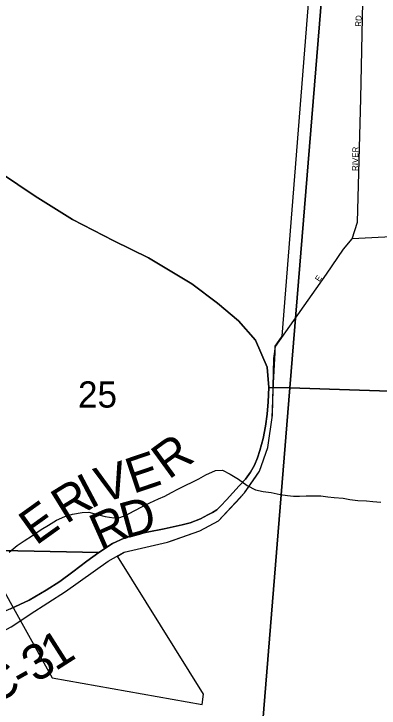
# Model space of a CAD drawing. Extents: x 1310247 to 1552180, y 377264 to 706493.
# Drawn here: x 1372833 to 1375909, y 486127 to 491975 of the extents above; entities that cross this region are included whole.
import ezdxf

# ---------------------------------------------------------------- set-up
doc = ezdxf.new("R2010")
doc.units = 0
for name, color, linetype in [('GM_X_City_Street', 7, 'Continuous'), ('GM_X_City_Street_Text', 7, 'Continuous'), ('GM_X_Corporation', 7, 'Continuous'), ('GM_X_County_Road', 7, 'Continuous'), ('GM_X_County_Road_Text', 7, 'Continuous'), ('GM_X_Minor_River', 7, 'Continuous'), ('GM_X_Section', 7, 'Continuous'), ('GM_X_Section_Text', 7, 'Continuous')]:
    doc.layers.add(name, color=color, linetype=linetype)

msp = doc.modelspace()

# ---------------------------------------------------------------- linework, layer by layer
at = {"layer": 'GM_X_City_Street'}
for points in [[(1374750.8, 487912.4), (1374776.6, 487940.1), (1374902.9, 488122.1), (1374971.4, 488323.4), (1375011.3, 488593.5), (1375021.6, 489073.1), (1375037.8, 489173.1), (1375466.1, 489782.4), (1375609.1, 489994.1), (1375683.2, 490078.9), (1375728.4, 490220.4), (1375754.8, 491261.6), (1375772.4, 492076.2), (1375835.7, 492588.6), (1375838.8, 492613.5)], [(1376450.1, 490120.6), (1375683.2, 490078.9)]]:
    msp.add_lwpolyline(points, dxfattribs=at)
at = {"layer": 'GM_X_Corporation'}
msp.add_lwpolyline([(1372670.3, 487253), (1373156, 486381.8), (1374419.7, 486157.1), (1374430, 486244.6), (1373704.6, 487408.3), (1373762.9, 487441.4), (1374127.8, 487524.1), (1374400.7, 487620.8), (1374556.9, 487703.8), (1374701, 487858.8), (1374776.6, 487940.1), (1374868.7, 488073.7), (1374902.9, 488122.1), (1374971.4, 488323.4), (1375007.6, 488573.7), (1375020.8, 488865.3), (1375034, 489123.8), (1375033.4, 489175.1), (1375092.3, 489259.4), (1375496.8, 494371.1)], dxfattribs=at)
at = {"layer": 'GM_X_County_Road'}
for points in [[(1374200, 487549.7), (1374400.7, 487620.8), (1374556.9, 487703.8), (1374741.2, 487902), (1374750.8, 487912.4)], [(1372970.9, 486917.2), (1373268.3, 487110.5), (1373626.8, 487364), (1373762.9, 487441.4), (1374127.8, 487524.1), (1374186.2, 487544.8), (1374200, 487549.7)], [(1372470.8, 486645.1), (1372561, 486679.8), (1372810.6, 486813), (1372950.1, 486903.7), (1372970.9, 486917.2)]]:
    msp.add_lwpolyline(points, dxfattribs=at)
at = {"layer": 'GM_X_Minor_River'}
msp.add_lwpolyline([(1372792.2, 487440.7), (1372860, 487497.1), (1372919.2, 487535.7), (1372988.7, 487580.1), (1373064.3, 487630.3), (1373123.5, 487666.8), (1373190.9, 487711.2), (1373262, 487741.5), (1373326.7, 487759.8), (1373407.3, 487773.7), (1373465.6, 487776.2), (1373537.4, 487758.2), (1373603.2, 487742.3), (1373675.1, 487730.3), (1373725.3, 487733), (1373780.1, 487753.6), (1373845.3, 487790), (1373916.5, 487826.3), (1373977.5, 487856.8), (1374050.7, 487891), (1374103.5, 487913.7), (1374160.5, 487942.3), (1374213.5, 487971), (1374276.5, 488003.5), (1374339.6, 488033.9), (1374390.4, 488058.7), (1374449.5, 488091.2), (1374530.8, 488129.2), (1374591.1, 488131.6), (1374654.4, 488097.7), (1374725.5, 488055.6), (1374798.3, 488001.4), (1374867.5, 487965.4), (1374931.4, 487951.6), (1374999.4, 487943.7), (1375077.2, 487927.6), (1375137.2, 487917.9), (1375187.2, 487912.5), (1375239.4, 487913.1), (1375293.6, 487915.7), (1375365.9, 487915.8), (1375418, 487914.3), (1375476, 487906.8), (1375530, 487901.3), (1375606.1, 487895.2), (1375664, 487883.6), (1375730, 487875.8), (1375804.2, 487871.8), (1375856.3, 487868.3), (1375924.3, 487860.5)], dxfattribs=at)
at = {"layer": 'GM_X_Section'}
for points in [[(1375560.3, 493789.5), (1381056.6, 494047.8), (1380602.9, 488643.8), (1375156.7, 488824.4)], [(1375156.7, 488824.4), (1380602.9, 488643.8), (1380084.6, 483209.4), (1374727.4, 483521.8)], [(1372181.4, 487466.3), (1373548.9, 487439), (1373447.2, 487365.3), (1373329.1, 487276), (1373219.2, 487192.5), (1373105.5, 487119.1), (1372961.6, 487036.4), (1372804, 486964), (1372644.4, 486895.7), (1372410.4, 486809), (1372380, 486791.7), (1372343.5, 486768.5), (1372305.2, 486757.4), (1372258.9, 486744.4), (1372166.5, 486726.6)]]:
    msp.add_lwpolyline(points, close=True, dxfattribs=at)
for points in [[(1375560.3, 493789.5), (1375156.7, 488824.4), (1374980.7, 488828.4), (1374966.6, 488998.7), (1374867.9, 489227), (1374725.6, 489390.3), (1374549, 489538.3), (1374332.7, 489701.3), (1373967.7, 489919.6), (1373674.9, 490064.3), (1373327, 490242.3), (1373013.5, 490439.5), (1372719.9, 490636.2)], [(1372719.9, 490636.2), (1373013.5, 490439.5), (1373327, 490242.3), (1373674.9, 490064.3), (1373967.7, 489919.6), (1374332.7, 489701.3), (1374549, 489538.3), (1374725.6, 489390.3), (1374867.9, 489227), (1374966.6, 488998.7), (1374980.7, 488828.4), (1374976, 488706.5), (1374967.6, 488602.7), (1374953.3, 488501), (1374932.9, 488399.4), (1374904.6, 488296.1), (1374885.2, 488234.5), (1374859.7, 488173.1), (1374826.4, 488113.8), (1374783.1, 488056.9), (1374729.7, 487998.1), (1374678.5, 487941.2), (1374625.1, 487882.4), (1374575.9, 487829.6), (1374541.2, 487798.3), (1374506.6, 487775.1), (1374466.2, 487754.1), (1374405.4, 487721.5), (1374318.6, 487687.4), (1374250.2, 487671), (1374099.5, 487638.4), (1373956.8, 487609.7), (1373854.3, 487588), (1373761.6, 487558.2), (1373664.6, 487512.4), (1373548.9, 487439), (1372181.4, 487466.3)], [(1372804, 486964), (1372961.6, 487036.4), (1373105.5, 487119.1), (1373219.2, 487192.5), (1373329.1, 487276), (1373447.2, 487365.3), (1373548.9, 487439), (1373664.6, 487512.4), (1373761.6, 487558.2), (1373854.3, 487588), (1373956.8, 487609.7), (1374099.5, 487638.4), (1374250.2, 487671), (1374318.6, 487687.4), (1374405.4, 487721.5), (1374466.2, 487754.1), (1374506.6, 487775.1), (1374541.2, 487798.3), (1374575.9, 487829.6), (1374625.1, 487882.4), (1374678.5, 487941.2), (1374729.7, 487998.1), (1374783.1, 488056.9), (1374826.4, 488113.8), (1374859.7, 488173.1), (1374885.2, 488234.5), (1374904.6, 488296.1), (1374932.9, 488399.4), (1374953.3, 488501), (1374967.6, 488602.7), (1374976, 488706.5), (1374980.7, 488828.4), (1375156.7, 488824.4), (1374727.4, 483521.8)]]:
    msp.add_lwpolyline(points, dxfattribs=at)

# ---------------------------------------------------------------- texts
at = {"layer": 'GM_X_City_Street_Text'}
for s, rotation, p in [('RD', 86.98614, (1375757.4, 491866.2)), ('RIVER', 88.89889, (1375731, 490651.5)), ('E', 56.31413, (1375407, 489714.9))]:
    msp.add_text(s, height=50, rotation=rotation, dxfattribs=at).set_placement(p)
at = {"layer": 'GM_X_County_Road_Text'}
for s, rotation, p in [('R', 36.07267, (1374137.1, 488046.8)), ('E', 18.73985, (1373838.4, 487930.1)), ('V', 16.18808, (1373571.2, 487852.2)), ('I', 27.95195, (1373477.5, 487800.5)), ('R', 31.69354, (1373272.3, 487673.7)), ('E', 35.66833, (1373019.5, 487492)), ('D', 15.45152, (1373773.9, 487553.4)), ('R', 23.94901, (1373559.8, 487457.4)), ('1', 32.54958, (1373181.6, 486434.6)), ('3', 31.19259, (1373016.9, 486334.8)), ('C', 22.75452, (1372639.4, 486157.2)), ('-', 29.37702, (1372900.6, 486269.1))]:
    msp.add_text(s, height=300, rotation=rotation, dxfattribs=at).set_placement(p)
at = {"layer": 'GM_X_Section_Text'}
msp.add_text('25', height=221, rotation=0.00001, dxfattribs=at).set_placement((1373373.2, 488658.5))

doc.saveas('drawing.dxf')
